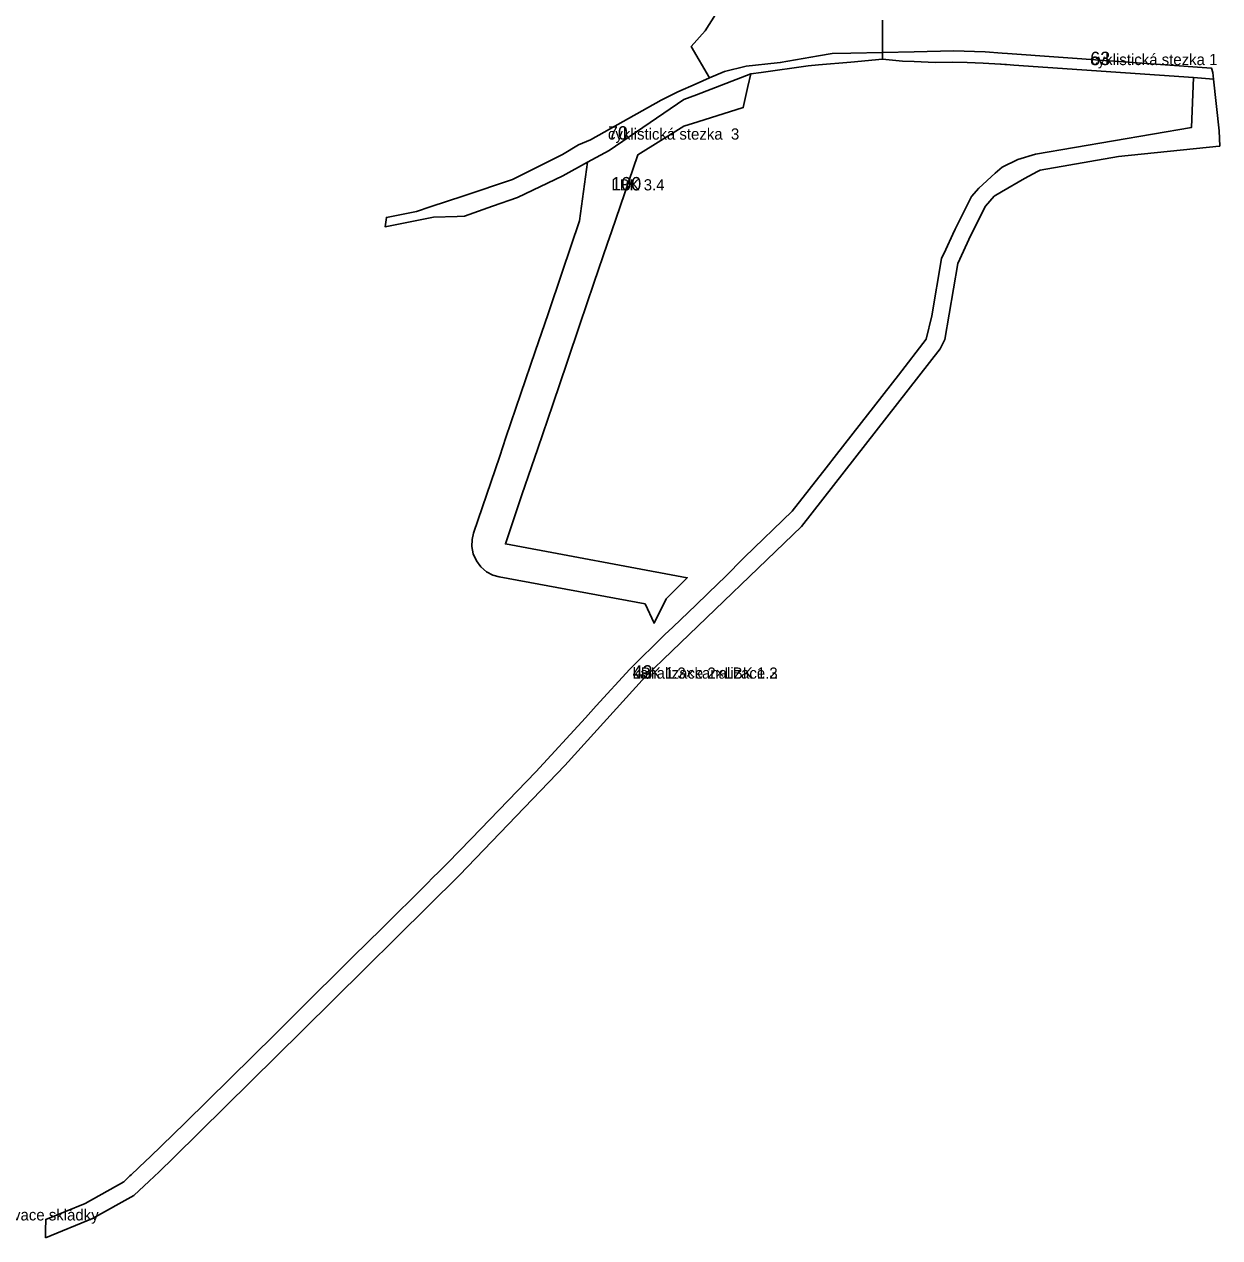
# Model space of a CAD drawing. Extents: x -535270 to -532834, y -1165802 to -1163869.
# Drawn here: x -534261 to -533727, y -1165342 to -1164800 of the extents above; entities that cross this region are included whole.
import ezdxf

# ---------------------------------------------------------------- set-up
doc = ezdxf.new("R2010")
doc.units = 0
for name, color, linetype in [('96070023', 7, 'Continuous'), ('96120023', 7, 'Continuous'), ('96140023', 7, 'Continuous'), ('ID_VPO', 7, 'Continuous'), ('ID_VPS', 7, 'Continuous')]:
    doc.layers.add(name, color=color, linetype=linetype)

msp = doc.modelspace()

# ---------------------------------------------------------------- linework, layer by layer
at = {"layer": '96120023'}
msp.add_lwpolyline([(-533877.62, -1164797.66), (-533877.61, -1164812.17), (-533891.74, -1164812.48), (-533900.11, -1164812.65), (-533906.24, -1164813.72), (-533923.29, -1164816.69), (-533924.69, -1164816.71), (-533938.49, -1164818.24), (-533948.29, -1164820.59), (-533954.92, -1164823.49), (-533963.1, -1164809.55), (-533956.94, -1164802.51), (-533952.29, -1164795.25)], dxfattribs=at)
for points in [[(-533891.71, -1164816.42), (-533906.18, -1164817.69), (-533910.91, -1164818.11), (-533931.85, -1164821.09), (-533936.53, -1164821.76), (-533960.78, -1164831.03), (-533966.36, -1164833.16), (-533999.79, -1164855.92), (-534009.46, -1164861.21), (-534020.45, -1164867.23), (-534040.68, -1164877.03), (-534051.9, -1164880.92), (-534064.45, -1164885.27), (-534067.68, -1164885.4), (-534078.33, -1164885.8), (-534099.92, -1164890.03), (-534099.32, -1164885.91), (-534085.85, -1164883.22), (-534079.77, -1164881.2), (-534064.74, -1164876.21), (-534042.95, -1164868.98), (-534020.66, -1164857.69), (-534013.44, -1164853.47), (-534008.11, -1164851.18), (-533976.56, -1164833.46), (-533969.12, -1164829.71), (-533960.9, -1164826.11), (-533954.92, -1164823.49), (-533948.29, -1164820.59), (-533938.49, -1164818.24), (-533924.69, -1164816.71), (-533923.29, -1164816.69), (-533906.24, -1164813.72), (-533900.11, -1164812.65), (-533891.74, -1164812.48), (-533877.61, -1164812.17), (-533877.62, -1164815.18)], [(-533863.45, -1164811.86), (-533845.93, -1164811.47), (-533831.76, -1164811.89), (-533824.09, -1164812.44), (-533821.72, -1164812.62), (-533730.54, -1164819.23), (-533730.04, -1164821.1), (-533729.7, -1164824.13), (-533738.69, -1164823.39), (-533818.85, -1164817.83), (-533822.16, -1164817.6), (-533822.99, -1164817.54), (-533824.57, -1164817.42), (-533824.73, -1164817.41), (-533824.86, -1164817.4), (-533832.62, -1164816.87), (-533839.71, -1164816.66), (-533846.11, -1164816.48), (-533854.09, -1164816.65), (-533863.51, -1164816.25), (-533868.67, -1164816.03), (-533877.62, -1164815.18), (-533877.61, -1164812.17)], [(-534251.77, -1165341.96), (-534251.69, -1165338.72), (-534251.58, -1165333.78), (-534233.96, -1165326.61), (-534216.74, -1165316.93), (-534213.98, -1165314.34), (-534213.44, -1165313.82), (-534206.83, -1165307.61), (-534205.1, -1165305.99), (-534189.23, -1165290.59), (-534149.08, -1165250.94), (-534139.47, -1165241.41), (-534114.18, -1165216.32), (-534101.59, -1165203.84), (-534081.18, -1165183.6), (-534078.55, -1165181), (-534075.93, -1165178.39), (-534072.06, -1165174.55), (-534061.51, -1165163.6), (-534032.62, -1165133.64), (-534010.38, -1165109.6), (-534005.54, -1165104.27), (-533990.61, -1165087.81), (-533974.83, -1165072.38), (-533971.32, -1165069), (-533960.95, -1165059.02), (-533950.89, -1165049.34), (-533948.25, -1165046.8), (-533939.32, -1165037.78), (-533917.98, -1165017.22), (-533902.84, -1164997.81), (-533898.23, -1164991.91), (-533884.32, -1164974.09), (-533870.47, -1164956.34), (-533858.16, -1164940.26), (-533855.51, -1164929.84), (-533851.21, -1164904.25), (-533849.34, -1164900.16), (-533846.25, -1164893.43), (-533845.18, -1164891.1), (-533837.81, -1164876.57), (-533834.51, -1164872.77), (-533827.21, -1164866.03), (-533824.16, -1164863.42), (-533817.17, -1164859.96), (-533809.26, -1164857.54), (-533739.47, -1164845.64), (-533738.69, -1164823.39), (-533729.7, -1164824.13), (-533727.12, -1164847.21), (-533726.9, -1164854), (-533727.16, -1164854.1), (-533772.11, -1164858.69), (-533807.19, -1164864.79), (-533808.27, -1164865.36), (-533814.12, -1164868.44), (-533824.38, -1164874.44), (-533827.73, -1164876.4), (-533831.54, -1164880.79), (-533838.18, -1164893.83), (-533843.98, -1164906.47), (-533849.69, -1164940.46), (-533851.83, -1164944.65), (-533913.79, -1165024.04), (-533971.79, -1165079.79), (-533983.52, -1165091.15), (-534019.59, -1165130.92), (-534066.72, -1165179.82), (-534136.8, -1165249.37), (-534194.29, -1165306.12), (-534200.89, -1165312.54), (-534205.31, -1165316.61), (-534212.27, -1165323.02), (-534230.69, -1165333.38)]]:
    msp.add_lwpolyline(points, close=True, dxfattribs=at)
at = {"layer": '96140023'}
for points in [[(-534251.77, -1165341.96), (-534251.69, -1165338.72), (-534251.58, -1165333.78), (-534233.96, -1165326.61), (-534216.74, -1165316.93), (-534213.98, -1165314.34), (-534213.44, -1165313.82), (-534206.83, -1165307.61), (-534205.1, -1165305.99), (-534189.23, -1165290.59), (-534149.08, -1165250.94), (-534139.47, -1165241.41), (-534114.18, -1165216.32), (-534101.59, -1165203.84), (-534081.18, -1165183.6), (-534078.55, -1165181), (-534075.93, -1165178.39), (-534072.06, -1165174.55), (-534061.51, -1165163.6), (-534032.62, -1165133.64), (-534010.38, -1165109.6), (-534005.54, -1165104.27), (-533990.61, -1165087.81), (-533974.83, -1165072.38), (-533971.32, -1165069), (-533960.95, -1165059.02), (-533950.89, -1165049.34), (-533948.25, -1165046.8), (-533939.32, -1165037.78), (-533917.98, -1165017.22), (-533902.84, -1164997.81), (-533898.23, -1164991.91), (-533884.32, -1164974.09), (-533870.47, -1164956.34), (-533858.16, -1164940.26), (-533855.51, -1164929.84), (-533851.21, -1164904.25), (-533849.34, -1164900.16), (-533846.25, -1164893.43), (-533845.18, -1164891.1), (-533837.81, -1164876.57), (-533834.51, -1164872.77), (-533827.21, -1164866.03), (-533824.16, -1164863.42), (-533817.17, -1164859.96), (-533809.26, -1164857.54), (-533739.47, -1164845.64), (-533738.69, -1164823.39), (-533729.7, -1164824.13), (-533727.12, -1164847.21), (-533726.9, -1164854), (-533727.16, -1164854.1), (-533772.11, -1164858.69), (-533807.19, -1164864.79), (-533808.27, -1164865.36), (-533814.12, -1164868.44), (-533824.38, -1164874.44), (-533827.73, -1164876.4), (-533831.54, -1164880.79), (-533838.18, -1164893.83), (-533843.98, -1164906.47), (-533849.69, -1164940.46), (-533851.83, -1164944.65), (-533913.79, -1165024.04), (-533971.79, -1165079.79), (-533983.52, -1165091.15), (-534019.59, -1165130.92), (-534066.72, -1165179.82), (-534136.8, -1165249.37), (-534194.29, -1165306.12), (-534200.89, -1165312.54), (-534205.31, -1165316.61), (-534212.27, -1165323.02), (-534230.69, -1165333.38)], [(-533936.53, -1164821.76), (-533937.75, -1164827.32), (-533939.82, -1164836.77), (-533960.22, -1164843.18), (-533966.45, -1164845.14), (-533986.98, -1164857.88), (-533998.79, -1164892.25), (-534000.56, -1164897.43), (-534006.6, -1164915.2), (-534012.88, -1164933.73), (-534018.61, -1164950.58), (-534025.02, -1164969.45), (-534031.7, -1164989.14), (-534034.52, -1164997.43), (-534038.74, -1165009.88), (-534046.17, -1165031.8), (-533964.89, -1165046.93), (-533974.3, -1165056.33), (-533979.67, -1165067.29), (-533983.72, -1165058.68), (-534048.92, -1165046.54), (-534051.75, -1165045.72), (-534054.54, -1165044.25), (-534057.07, -1165042.1), (-534059.11, -1165039.38), (-534060.49, -1165036.27), (-534061.12, -1165033.01), (-534061.05, -1165029.85), (-534060.38, -1165026.98), (-534048.72, -1164992.61), (-534045.9, -1164984.31), (-534039.22, -1164964.63), (-534032.81, -1164945.75), (-534027.08, -1164928.91), (-534020.8, -1164910.38), (-534012.98, -1164887.4), (-534009.46, -1164861.21), (-533999.79, -1164855.92), (-533966.36, -1164833.16), (-533960.78, -1164831.03)]]:
    msp.add_lwpolyline(points, close=True, dxfattribs=at)

# ---------------------------------------------------------------- texts
at = {"layer": '96070023'}
msp.add_text('rekultivace skládky', height=5, rotation=360, dxfattribs=at).set_placement((-534284.05, -1165334.24))
at = {"layer": '96120023'}
for s, rotation, p in [('cyklistická stezka 1', 360, (-533784.78, -1164817.8)), ('cyklistická stezka  3', 360, (-534000.34, -1164851.1)), ('kanalizace 2×LBK 1.3', 0, (-533989.34, -1165092.06))]:
    msp.add_text(s, height=5, rotation=rotation, dxfattribs=at).set_placement(p)
at = {"layer": '96140023'}
for s, p in [('LBK 3.4', (-533998.83, -1164873.81)), ('LBK 1.3×kanalizace 2', (-533989.34, -1165092.06))]:
    msp.add_text(s, height=5, rotation=0, dxfattribs=at).set_placement(p)
at = {"layer": 'ID_VPO'}
for s, rotation, p in [('100', 360, (-533998.83, -1164873.81)), ('43', 0, (-533989.34, -1165092.06))]:
    msp.add_text(s, height=6, rotation=rotation, dxfattribs=at).set_placement(p)
at = {"layer": 'ID_VPS'}
for s, rotation, p in [('63', 360, (-533784.78, -1164817.8)), ('70', 360, (-534000.34, -1164851.1)), ('43', 0, (-533989.34, -1165092.06))]:
    msp.add_text(s, height=6, rotation=rotation, dxfattribs=at).set_placement(p)

doc.saveas('drawing.dxf')
